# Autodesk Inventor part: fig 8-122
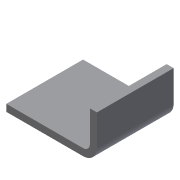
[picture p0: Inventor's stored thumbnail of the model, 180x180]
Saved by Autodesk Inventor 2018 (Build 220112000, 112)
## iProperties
Created: 2009-09
Part Number: fig 8-122
Document SubType Name: Modeling
Designer: Sham
Density: 1 g/cm^3
Material: Generic
Appearance: Default
Author: Sham
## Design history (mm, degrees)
sketch "Sketch1"
  geometry: L1 (-33.976, 22)-(0, 22); L2 (0, 22)-(0, 0); L3 (0, 0)-(-33.976, 0); L4 (-33.976, 0)-(-33.976, 22)
  constraints: 8 end point, 2 parallel, 1 horizontal, 1 perpendicular
extrude "Extrusion1" new body sketch "Sketch1" distance "d0" = 2; taper "d1" = 0 deg
sketch "Sketch2"
  geometry: L1 (-12, 22)-(-12, 0)
  constraints: 2 end point
feature "Bend Part1" sketch "Sketch2" dims "d5" = 90 deg, "d6" = 2
body "Solid1"
